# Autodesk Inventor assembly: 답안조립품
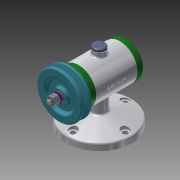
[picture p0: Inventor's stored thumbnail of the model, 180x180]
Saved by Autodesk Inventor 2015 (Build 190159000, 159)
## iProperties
Created: 2018-12
Part Number: 답안조립품
Document SubType Name: Assembly
Designer: now060
Author: now060
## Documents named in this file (15)
- C:\Users\now060\Desktop\481207V1070\답안조립품.iam
- C:\Users\now060\Desktop\481207V1070\V벨트풀리.ipt
- C:\Users\now060\Desktop\481207V1070\키 3 x 3 x 12.ipt
- C:\Users\now060\Desktop\481207V1070\고무캡.ipt
- C:\Users\now060\Desktop\481207V1070\너트 M8.ipt
- 너트 M8.ipt
- C:\Users\now060\Desktop\481207V1070\뒤커버.ipt
- C:\Users\now060\Desktop\481207V1070\베어링 15 x 32 x 9.ipt
- C:\Users\now060\Desktop\481207V1070\본체.ipt
- C:\Users\now060\Desktop\481207V1070\볼트 M4 x 12.ipt
- C:\Users\now060\Desktop\481207V1070\스프링와셔 8.ipt
- C:\Users\now060\Desktop\481207V1070\앞커버.ipt
- C:\Users\now060\Desktop\481207V1070\오일 실 15 25 7.ipt
- C:\Users\now060\Desktop\481207V1070\와셔 8x17.ipt
- C:\Users\now060\Desktop\481207V1070\축.ipt
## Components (2 placed, 2 different names)
1. V벨트풀리:1 — 각도:2
2. 고무캡:1
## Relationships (1: Angle 1)
- 각도:2 [Angle]: V벨트풀리:1
